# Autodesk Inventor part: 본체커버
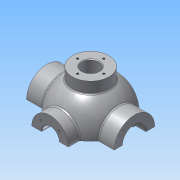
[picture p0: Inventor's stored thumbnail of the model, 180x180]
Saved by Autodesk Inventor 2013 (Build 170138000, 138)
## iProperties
Created: 2015-12
Part Number: 본체커버
Material: 알루미늄 6061
Document SubType Name: Modeling
Designer: mduedu
Density: 2.71 g/cm^3
Mass: 574.084 g
Surface Area: 451.737 cm^2
Volume: 211.839 cm^3
Author: mduedu
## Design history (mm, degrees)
sketch "스케치1"
  geometry: L1 (-53, 0)-(53, 0); A1 r 53 centre (0, 0) between (53, 0) and (-53, 0); 2 further points
  constraints: 2 coincident, 2 end point, 2 point on circle, 1 centre point, 1 horizontal, 1 midpoint
  dimensions: "d0" = 53 radius of A1
revolve "회전1" sketch "스케치1" stored, may be unused: angle "d2" = 90 deg
feature "쉘1" dims "d11" = 10
node "작업 평면1"
sketch "스케치2"
  geometry: C1 r 31 at (0, 0); 1 further point
  constraints: 1 centre point, 1 coincident
  dimensions: "d4" = 62 diameter of C1
extrude "돌출1" join sketch "스케치2" stored distance "d5" = 10; taper "d6" = 0 deg
node "작업 평면2"
sketch "스케치3"
  geometry: C1 r 28 at (0, 0); 1 further point
  constraints: 1 centre point, 1 coincident
  dimensions: "d8" = 56 diameter of C1
extrude "돌출2" join sketch "스케치3" stored distance "d9" = 10; taper "d10" = 0 deg
hole "구멍1" diameter "d14" = 35; stored, may be unused: countersink angle "d18" = 90 deg, drill point angle "d20" = 0 deg; dims "d12" = 10, "d13" = 10, "d15" = 6, "d16" = 4, "d17" = 2, "d19" = 16
hole "구멍2" diameter "d23" = 27; stored, may be unused: countersink angle "d27" = 90 deg, drill point angle "d29" = 0 deg; dims "d21" = 10, "d22" = 10, "d24" = 6, "d25" = 4, "d26" = 2, "d28" = 16
fillet "모깎기1" dims "d30" = 0.3
hole "구멍3" diameter "d33" = 26; stored, may be unused: countersink angle "d37" = 90 deg, drill point angle "d39" = 0 deg; dims "d31" = 10, "d32" = 10, "d34" = 6, "d35" = 4, "d36" = 2, "d38" = 16
chamfer "모따기1" distance "d40" = 1; stored, may be unused: second distance "d41" = 2, angle "d42" = 45 deg
sketch "스케치4"
  geometry: L1 (0, 0)-(0, -25); L2 (0, 0)-(-17.678, -17.678); A1 r 25 centre (0, 0) between (-17.678, -17.678) and (0, -25); 1 further point
  constraints: 4 end point, 2 point on circle, 1 centre point, 1 coincident, 1 vertical
  dimensions: "d43" = 50 diameter of A1; "d47" = 45 deg angle of L1 L2
hole "구멍4" sketch "스케치4" at (-17.678, -17.678) diameter "d49" = 3.242; stored, may be unused: countersink angle "d53" = 90 deg, drill point angle "d55" = 118 deg; dims "d50" = 11, "d51" = 4, "d52" = 2, "d54" = 13
sketch "스케치5"
  geometry: L1 (0, 0)-(0, -20); L2 (0, 0)-(-14.142, -14.142); A1 r 20 centre (0, 0) between (0, -20) and (-14.142, -14.142); 2 further points
  constraints: 4 end point, 2 coincident, 2 point on circle, 1 centre point, 1 vertical
  dimensions: "d59" = 40 diameter of A1; "d65" = 45 deg angle of L1 L2
hole "구멍5" sketch "스케치5" at (-14.142, -14.142) diameter "d67" = 3.242; stored, may be unused: countersink angle "d71" = 90 deg, drill point angle "d73" = 118 deg; dims "d68" = 8, "d69" = 4, "d70" = 2, "d72" = 10
node "작업 평면3"
sketch "스케치6"
  geometry: C1 r 65 at (0, 0); 1 further point
  constraints: 1 centre point, 1 coincident
  dimensions: "d78" = 130 diameter of C1
extrude "돌출3" join sketch "스케치6" distance "d80" = 10; taper "d81" = 0 deg
sketch "스케치7"
  geometry: C1 r 20 at (0, 0); 1 further point
  constraints: 1 centre point, 1 coincident
  dimensions: "d82" = 40 diameter of C1
extrude "돌출4" join sketch "스케치7" stored distance "d84" = 10; taper "d85" = 0 deg
sketch "스케치8"
  geometry: 2 further points
  constraints: 1 coincident
hole "구멍6" sketch "스케치8" at (0, 0) diameter "d86" = 20; stored, may be unused: countersink angle "d90" = 90 deg, drill point angle "d92" = 118 deg; dims "d87" = 7, "d88" = 40, "d89" = 5, "d91" = 10
fillet "모깎기2" dims "d93" = 0.3
sketch "스케치9"
  geometry: L1 (65, -75)-(-65, -75) reference; L2 (-45, -75)-(-38.245, -36.692); A1 r 53 centre (0, 0) between (42.988, 31) and (42.988, -31) reference; 1 further point
  constraints: 2 end point, 1 point on circle, 1 point on line
  dimensions: "d94" = 45 horizontal distance of L2.start point (0, 0); "d95" = 80 deg angle of L2 L1
feature "리브1" sketch "스케치9" dims "d96" = 1, "d97" = 8, "d98" = 0, "d99" = 0, "d100" = 1, "d101" = 1
sketch "스케치10"
  geometry: L1 (0, 0)-(0, -55); L2 (0, 0)-(-38.891, -38.891); A1 r 55 centre (0, 0) between (0, -55) and (-38.891, -38.891); 2 further points
  constraints: 4 end point, 2 coincident, 2 point on circle, 1 centre point, 1 vertical
  dimensions: "d105" = 110 diameter of A1; "d107" = 45 deg angle of L1 L2
hole "구멍7" sketch "스케치10" at (-38.891, -38.891) diameter "d109" = 10; stored, may be unused: countersink angle "d113" = 90 deg, drill point angle "d115" = 118 deg; dims "d110" = 7, "d111" = 40, "d112" = 5, "d114" = 10
fillet "모깎기3" dims "d120" = 3
fillet "모깎기4" dims "d121" = 3, "d122" = 3
fillet "모깎기5" dims "d123" = 3
fillet "모깎기6" dims "d124" = 3
sketch "스케치11"
  geometry: C1 r 5 at (-38.891, 38.891) reference; C2 r 5 at (38.891, 38.891) reference; C3 r 5 at (38.891, -38.891) reference; C4 r 5 at (-38.891, -38.891) reference; C5 r 20 at (0, 0) reference; C6 r 65 at (0, 0) reference; 1 further point
  constraints: 3 other
feature "엠보싱1" sketch "스케치11" dims "d125" = 0.5, "d126" = 0
sketch "스케치12"
  geometry: L1 (0, 100)-(0, -100); L2 (0, 100)-(-150, 100); L3 (-150, 100)-(-150, -100); L4 (-150, -100)-(0, -100); 2 further points
  constraints: 8 end point, 3 perpendicular, 1 coincident, 1 midpoint, 1 vertical
  dimensions: "d127" = 200 distance of L2.end L3.end; "d129" = 150 distance of L3.end L1.end
extrude "돌출5" cut sketch "스케치12" stored distance "d130" = 10; taper "d131" = 0 deg
sketch "스케치13"
  geometry: C1 r 7 at (0, -53); A1 r 53 centre (0, 0) between (-42.113, -32.179) and (42.113, -32.179) reference; 1 further point
  constraints: 1 centre point, 1 point on circle
  dimensions: "d132" = 14 diameter of C1
extrude "돌출6" join sketch "스케치13" distance "d133" = 5; taper "d134" = 0 deg
sketch "스케치14"
  geometry: C1 r 7 at (0, 0) reference; 1 further point
extrude "돌출7" cut sketch "스케치14" stored distance "d135" = 5; taper "d136" = 0 deg
sketch "스케치15"
  geometry: C1 r 2.25 at (0, 53); A1 r 7 centre (0, 53) between (6.965, 52.302) and (-6.965, 52.302) reference; 1 further point
  constraints: 1 centre point, 1 coincident
  dimensions: "d139" = 4.5 diameter of C1
extrude "돌출8" cut sketch "스케치15" stored distance "d141" = 5; taper "d142" = 0 deg
fillet "모깎기7" dims "d143" = 3
fillet "모깎기8" dims "d144" = 1
fillet "모깎기9" dims "d145" = 1
fillet "모깎기10" dims "d146" = 1
node "작업 평면4"
sketch "스케치16"
  geometry: C1 r 28 at (0, 0); 1 further point
  constraints: 1 centre point, 1 coincident
  dimensions: "d148" = 56 diameter of C1
extrude "돌출9" join sketch "스케치16" stored distance "d150" = 5; taper "d151" = 0 deg
hole "구멍8" diameter "d154" = 26; stored, may be unused: countersink angle "d158" = 90 deg, drill point angle "d160" = 118 deg; dims "d152" = 10, "d153" = 10, "d155" = 6, "d156" = 4, "d157" = 2, "d159" = 8
sketch "스케치17" dims "d161" = 40
  geometry: 3 further points
  constraints: 2 vertical alignment, 1 coincident, 2 other
hole "구멍9" sketch "스케치17" at (0, 20) diameter "d163" = 3.242; stored, may be unused: countersink angle "d167" = 90 deg, drill point angle "d169" = 118 deg; dims "d164" = 8, "d165" = 4, "d166" = 2, "d168" = 10
fillet "모깎기11" dims "d173" = 3
chamfer "모따기2" distance "d174" = 1; stored, may be unused: second distance "d175" = 2, angle "d176" = 45 deg
node "솔리드1"
mirror "대칭1"
mirror "대칭2"
pattern_circular "원형 패턴1" dims angle "d57" = 360 deg
mirror "대칭3"
pattern_circular "원형 패턴2" dims angle "d75" = 360 deg
pattern_circular "원형 패턴3" dims angle "d103" = 360 deg
pattern_circular "원형 패턴4" dims angle "d118" = 360 deg
pattern_circular "원형 패턴5" dims angle "d171" = 360 deg
node "투영된 루프1"
other parameters: "d3" = 67, "d7" = 62, "d77" = -85, "d147" = 62
